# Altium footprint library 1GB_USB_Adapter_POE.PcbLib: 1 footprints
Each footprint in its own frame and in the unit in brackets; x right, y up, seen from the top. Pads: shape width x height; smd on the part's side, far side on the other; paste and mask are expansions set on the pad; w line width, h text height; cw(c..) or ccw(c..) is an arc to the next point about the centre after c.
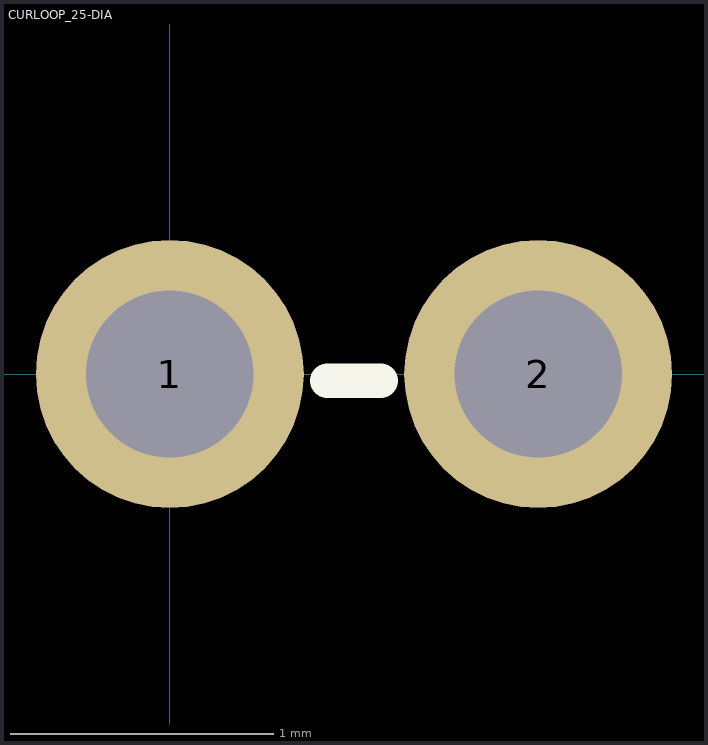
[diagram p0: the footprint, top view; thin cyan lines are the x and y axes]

## CURLOOP_25-DIA [mil]
pads (2):
  round 40 hole 25: 1(0,0) 2(55,0)
Top Overlay:
  lines w5.1: 23.5,-1 31.5,-1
